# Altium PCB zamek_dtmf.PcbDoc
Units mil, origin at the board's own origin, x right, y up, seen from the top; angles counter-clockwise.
Board outline 6000 x 4000 mil, 2 copper layers (Top Layer, Bottom Layer); 26 components, 24 nets, 83 pads, 5 vias.
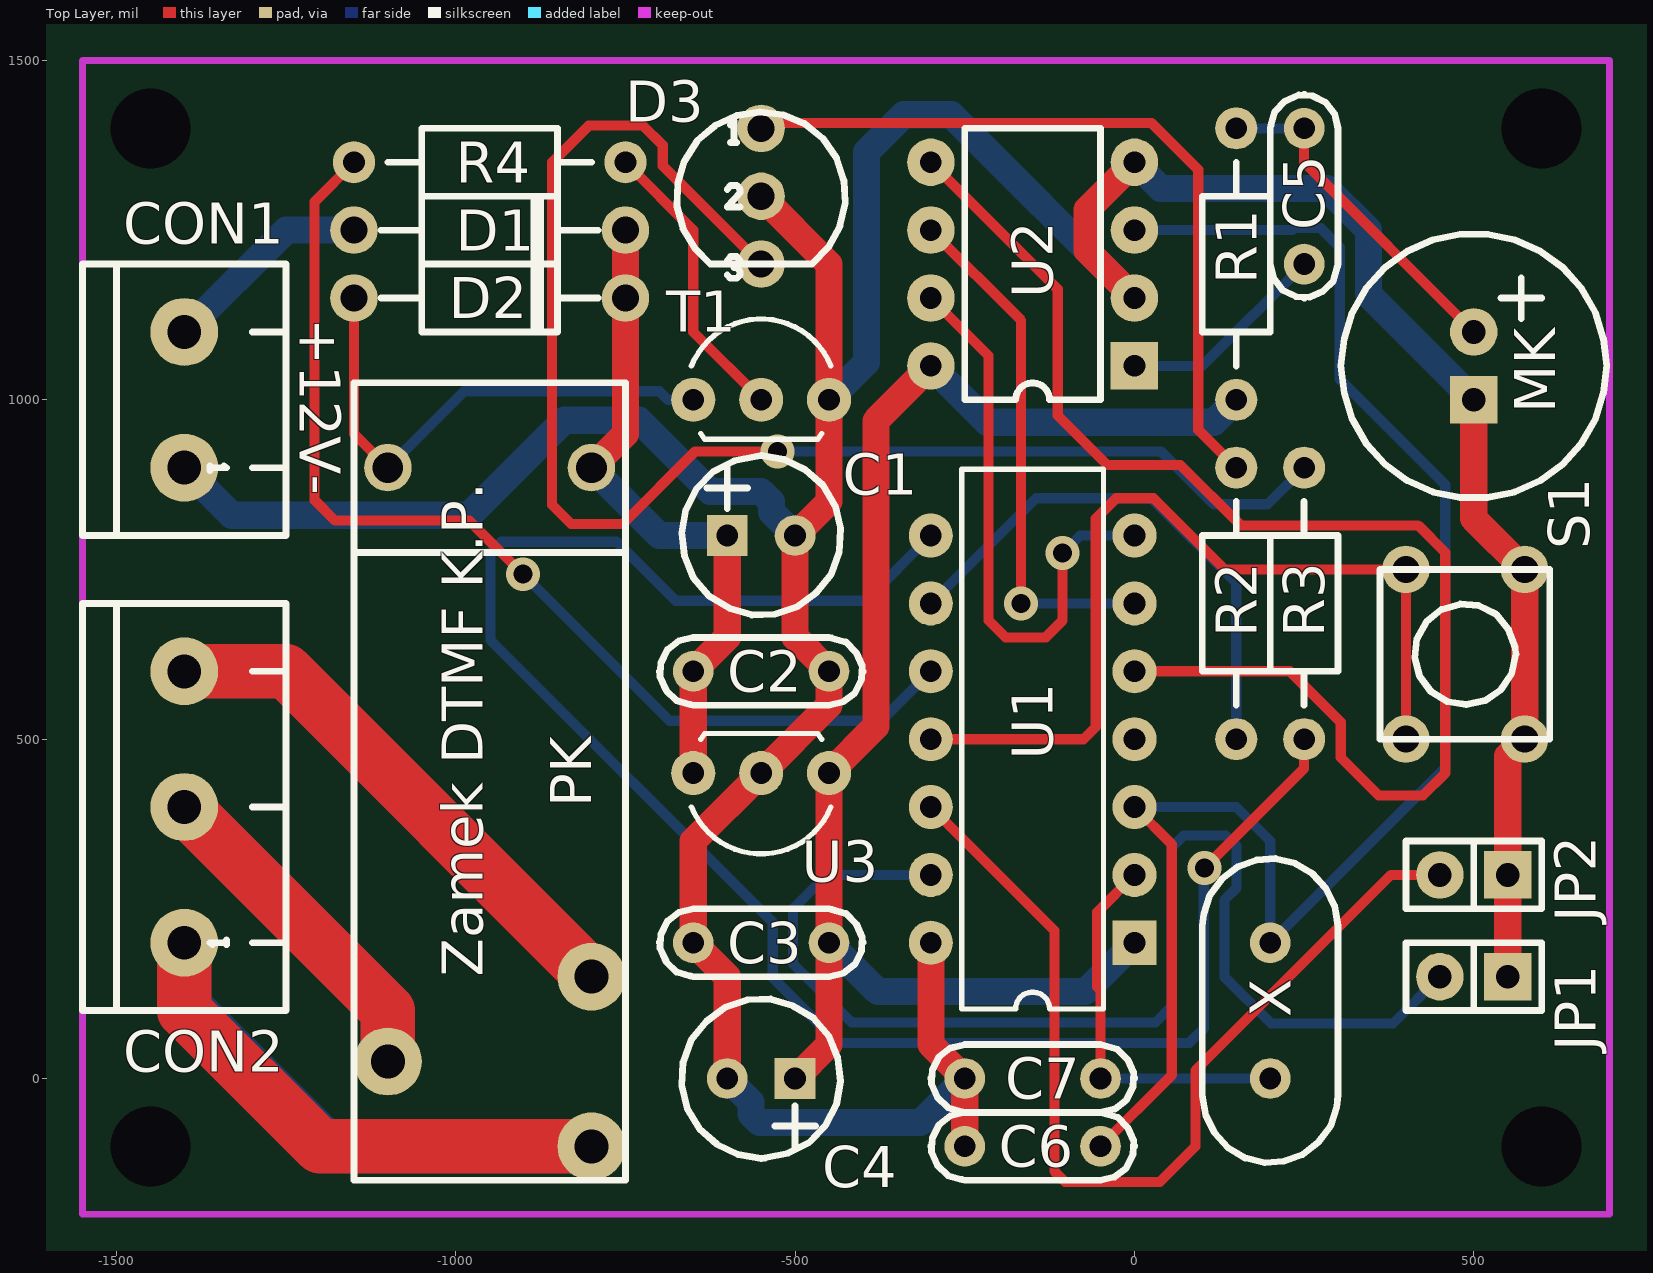
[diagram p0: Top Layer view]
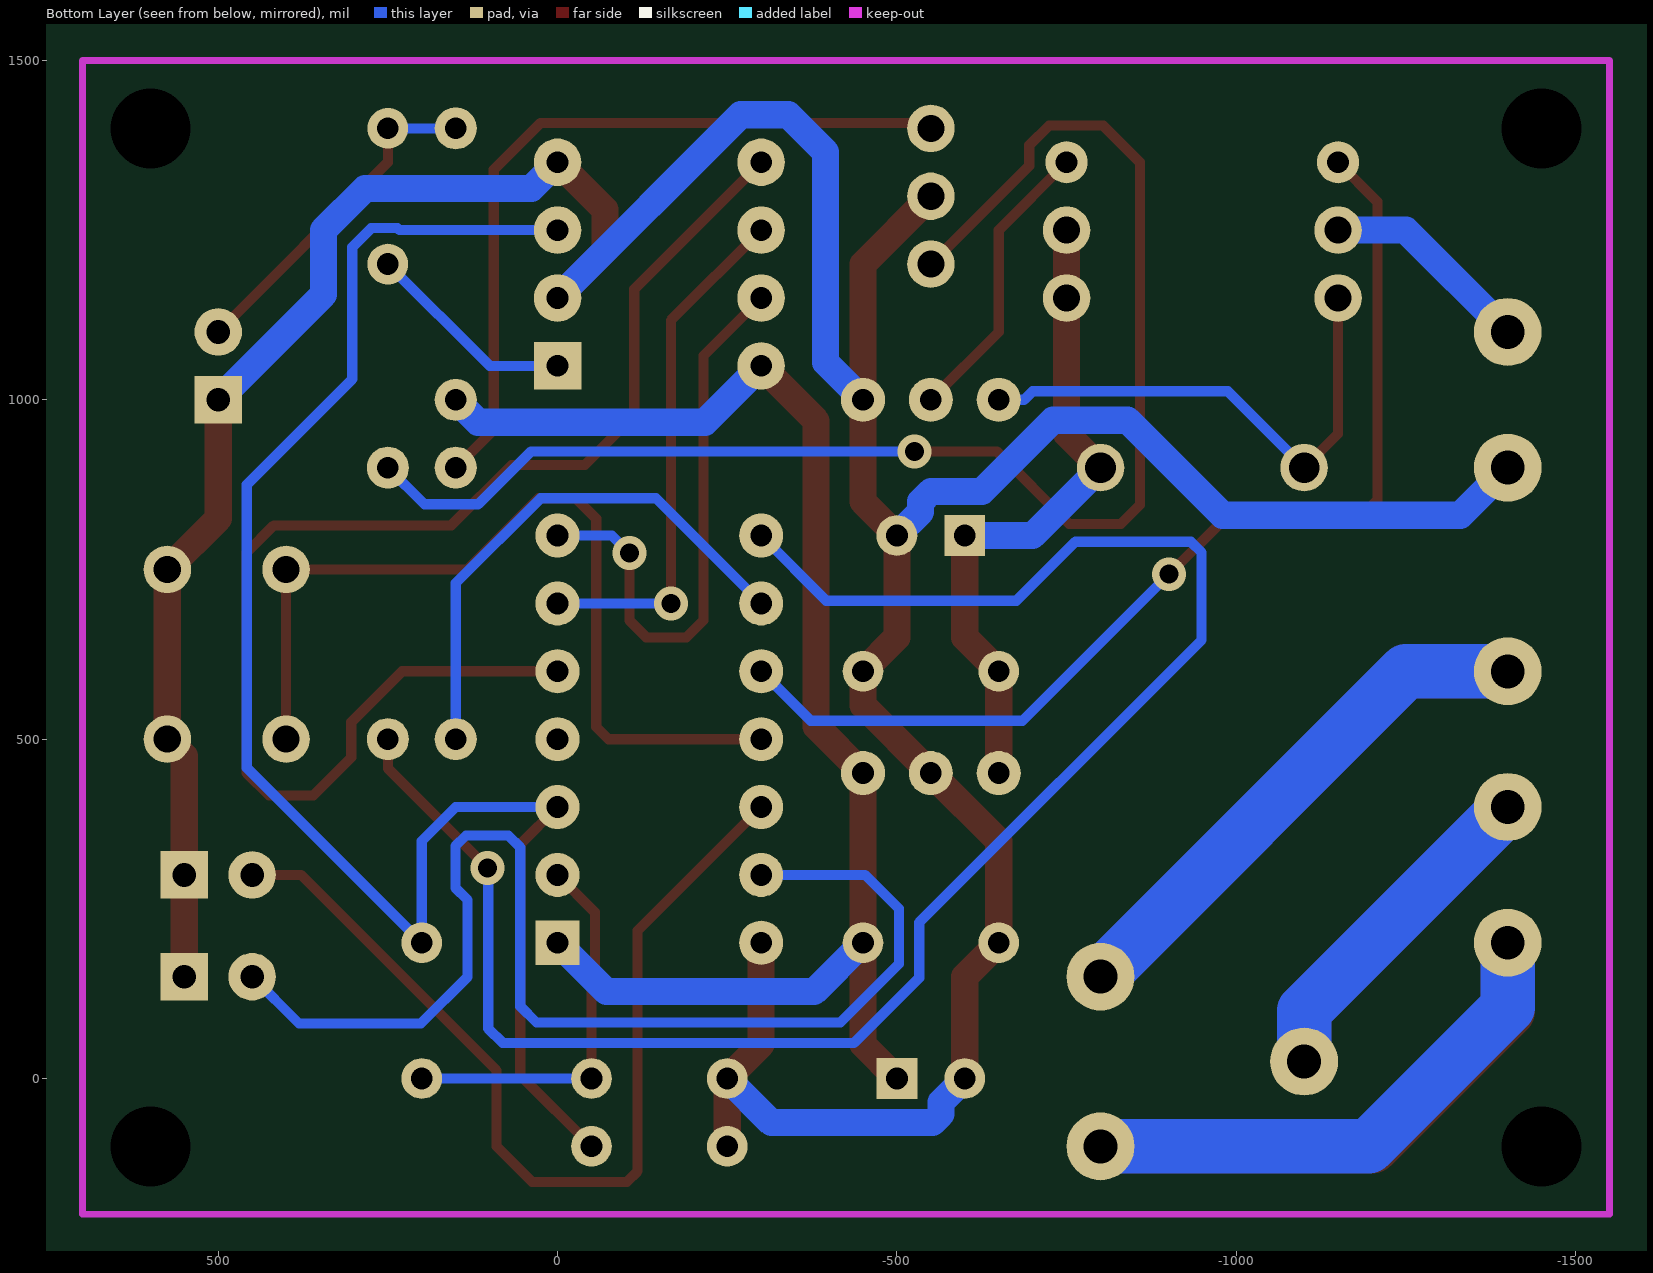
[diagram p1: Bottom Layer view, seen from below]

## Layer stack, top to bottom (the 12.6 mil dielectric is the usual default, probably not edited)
Top Layer: signal copper 1.4
Dielectric: dielectric 12.6, FR-4, Dk 4.8
Bottom Layer: signal copper 1.4

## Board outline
-2690,-1200 3310,-1200 3310,2800 -2690,2800

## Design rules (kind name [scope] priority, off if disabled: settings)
Clearance [All] p1: gap=20
ComponentClearance [All] p1: gap=10 collisioncheckmode=0
PolygonConnect [All] p1: connectstyle=Relief reliefconductorwidth=20 reliefentries=4 polygonreliefangle="90 Angle"
RoutingVias [All] p1: holewidth=28 width=50 viastyle="Through Hole" minholewidth=28 minwidth=50 maxholewidth=28 maxwidth=50
SolderMaskExpansion [All] p1: expansion=4
TestPointUsage [All] p1: valid=0 allowmultiple=FALSE
Testpoint [All] p1: side=15 testpointundercomponent=TRUE minsize=40 maxsize=100 preferedsize=60 minholesize=0 maxholesize=40 preferedholesize=32 testpointgrid=1 style=1023 order=-539222988
Width Width_2 [InNet('NetCON2_1') Or InNet('NetCON2_2') Or InNet('NetCON2_3')] p1: maxlimit=80 minlimit=10 preferedwidth=80
Width Width_1 [InNet('NetCON1_2') Or InNet('12V') Or InNet('GND') Or InNet('NetCON2_1') Or InNet('NetCON2_2') Or InNet('NetCON2_3') Or InNet('VCC')] p2: maxlimit=40 minlimit=10 preferedwidth=40
Width [All] p3: maxlimit=15 minlimit=10 preferedwidth=15
17 further rules are at their usual default settings.

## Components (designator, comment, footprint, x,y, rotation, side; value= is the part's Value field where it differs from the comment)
C1 "Cap Pol1" elektr1 -600,800 r90 top
C2 "Cap" cap1 -550,600 r180 top
C3 "Cap" cap1 -550,200 r0 top
C4 "Cap Pol1" elektr1 -500,0 r270 top
C5 "Cap" cap1 250,1300 r270 top
C6 "Cap" cap1 -150,-100 r0 top
C7 "Cap" cap1 -150,0 r0 top
CON1 "Header 2" con2-5 -1400,1000 r270 top
CON2 "Header 3" con3-5 -1400,400 r90 top
D1 "1N4007" dioda -950,1250 r0 top
D2 "1N4007" dioda -950,1150 r0 top
D3 "LED_2K" LED_2K -550,1400 r270 top
JP1 "JUMPER" SIP2 550,150 r180 top
JP2 "JUMPER" SIP2 550,300 r180 top
MK "Mic2" ELEKTR2 500,1050 r0 top
PK "RM96P-12" RM96P-12 -800,900 r90 top
R1 "Res2" r 150,1200 r270 top
R2 "Res2" R 150,700 r90 top
R3 "Res2" r 250,700 r90 top
R4 "Res2" r -950,1350 r0 top
S1 "SW-PB" key1 400,500 r0 top
T1 "BC547" TO-92C -650,1000 r90 top
U1 "PIC16F630-I/P" dip-14 -150,500 r90 top
U2 "MT3171BE" DIP8 0,1050 r180 top
U3 "78L05" TO-92C -450,450 r270 top
X "4,19MHz" xtal 200,100 r270 top

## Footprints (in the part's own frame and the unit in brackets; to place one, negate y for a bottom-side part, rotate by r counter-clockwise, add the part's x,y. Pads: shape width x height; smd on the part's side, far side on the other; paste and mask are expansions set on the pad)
cap1 [mil]
  round 60 hole 32: 1(-100,0) 2(100,0)
  silkscreen extent -150,-50 150,50
con2-5 [mil]
  round 100 hole 50: 1(100,0) 2(-100,0)
  silkscreen extent -200,-150 200,150
con3-5 [mil]
  round 100 hole 50: 1(-200,0) 2(0,0) 3(200,0)
  silkscreen extent -300,-150 300,150
dioda [mil]
  round 70 hole 40: 1(-200,0) 2(200,0)
  silkscreen extent -160,-50 160,50
DIP8 [mil]
  rect 70x70 hole 32: 1(0,0)
  round 70 hole 32: 2(0,-100) 3(0,-200) 4(0,-300) 5(300,-300) 6(300,-200) 7(300,-100) 8(300,0)
  silkscreen extent 50,-350 250,50
dip-14 [mil]
  rect 65x65 hole 32: 1(-300,-150)
  round 65 hole 32: 2(-200,-150) 3(-100,-150) 4(0,-150) 5(100,-150) 6(200,-150) 7(300,-150) 8(300,150) 9(200,150) 10(100,150) 11(0,150) 12(-100,150) 13(-200,150) 14(-300,150)
  silkscreen extent -398,-104 398,104
elektr1 [mil]
  rect 60x60 hole 32: 1(0,0)
  round 60 hole 32: 2(0,-100)
  silkscreen extent -117,-167 118,67
ELEKTR2 [mil]
  rect 70x70 hole 35: 1(0,-50)
  round 70 hole 35: 2(0,50)
  silkscreen extent -196,-194 196,194
key1 [mil]
  round 70 hole 40: 1(0,0) 1(0,250) 2(175,0) 2(175,250)
  silkscreen extent -38,0 212,250
LED_2K [mil]
  round 70 hole 40: 1(0,0) 2(100,0) 3(200,0)
  silkscreen extent -24,-124 221,124
r [mil]
  round 62 hole 32: 1(-200,0) 2(200,0)
  silkscreen extent -150,-50 150,50
R [mil]
  round 62 hole 32: 1(-200,0) 2(200,0)
  silkscreen extent -150,-50 150,50
RM96P-12 [mil]
  round 70 hole 45: 1(0,0) 2(0,300)
  round 100 hole 50: 3(-750,0) 4(-875,300) 5(-1000,0)
  silkscreen extent -1050,-50 125,350
SIP2 [mil]
  rect 70x70 hole 35: 1(0,0)
  round 70 hole 35: 2(100,0)
  silkscreen extent -50,-50 150,50
TO-92C [mil]
  round 65 hole 32: 1(0,0) 2(0,-100) 3(0,-200)
  silkscreen extent -58,-203 119,3
xtal [mil]
  round 60 hole 32: 1(-100,0) 2(100,0)
  silkscreen extent -224,-100 224,100

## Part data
C1 C4: library part ELECTRO2, "Electrolytic Capacitor"
C2 C3: library part CAP, "Capacitor"
C5 C6 C7: "Capacitor"
CON1: library part CON2, "Connector"
CON2: "Header, 3-Pin"
D1: library part DIODE, "Diode"
D2: library part LED1, "Typical RED GaAs LED"
D3: library part "Diode 1N4007", "1 Amp General Purpose Rectifier"
MK: "Microphone"
R1 R3 R4: "Resistor"
R2: library part "Res Adj2", "Variable Resistor"
S1: "Switch"
T1: library part NPN, "NPN Bipolar Transistor"
U1: library part PIC16F630-E/P, "FLASH-Based 8-Bit CMOS Microcontroller, 1K (x14-Bit words) FLASH, 64 Bytes SRAM, 14-Pin PDIP, 2.0 to 5.5V Supply Range, Extended Temperature"
U2: library part MT3170BE
U3: library part "Volt Reg", "Voltage Regulator"
X: library part XTAL, "Crystal Oscillator"

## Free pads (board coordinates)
  round 60 hole 118.11: 0(-1450,-100) 1(-1450,1400) 2(600,1400) 3(600,-100)

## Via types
v1: diameter 50, hole 28, Top Layer to Bottom Layer, 5 vias

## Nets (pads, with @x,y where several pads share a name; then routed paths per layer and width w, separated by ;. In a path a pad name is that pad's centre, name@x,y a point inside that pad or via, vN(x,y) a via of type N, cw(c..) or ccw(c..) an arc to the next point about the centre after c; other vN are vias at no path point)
12V: C1.1 C2.2 D1.2 D2.2 PK.1 U3.3 | length 982.8
  Top Layer w40: PK.1 -750,950 D2.2 D1.2 ; U3.3 C2.2 -600,650 C1.1
  Bottom Layer w40: PK.1 -700,800 C1.1
GND: C1.2 C2.1 C3.1 C4.2 C6.1 C7.1 CON1.1 D3.2 JP1.1 JP2.1 MK.1 S1.2 T1.3 U1.14 U2.2 U2.4 U3.2 | length 6054.8
  Top Layer w40: C4.2 -600,150 C3.1 -650,350 U3.2 -450,550 C2.1 -500,650 C1.2 -450,850 T1.3 -450,1200 D3.2 ; U1.14 -300,50 C7.1 C6.1 ; U2.2 -70,1220 -70,1280 U2.4 ; MK.1 500,825 575,750 575,500 550,475 JP2.1 JP1.1
  Bottom Layer w40: CON1.1 -1330,830 -980,830 -840,970 -730,970 -625,865 -550,865 -535,850 -535,835 C1.2 ; C4.2 -565,-35 -565,-52.5 -552.5,-65 -315,-65 C7.1 ; T1.3 -395,1055 -395,1365 -340,1420 -270,1420 U2.2 ; U2.4 38.58,1311.42 283.58,1311.42 345,1250 345,1155 MK.1
NetC5_1: C5.1 MK.2 R1.1 | length 503.6
  Top Layer w15: C5.1 250,1350 MK.2
  Bottom Layer w15: R1.1 C5.1
NetC5_2: C5.2 U2.1 | length 312.1
  Bottom Layer w15: U2.1 100,1050 C5.2
NetC6_2: C6.2 U1.3 U2.3 X.1 | length 2448.6
  Top Layer w15: C6.2 55,5 55,345 U1.3
  Bottom Layer w15: U1.3 150,400 200,350 X.1 458,458 458,875 302.5,1030.5 302.5,1225 274.5,1253 236,1253 233,1250 U2.3
NetC7_2: C7.2 U1.2 X.2 | length 574.9
  Top Layer w15: C7.2 -50,130 -55,135 -55,245 U1.2
  Bottom Layer w15: C7.2 X.2
NetCON1_2: CON1.2 D1.1 | length 312.1
  Bottom Layer w40: CON1.2 -1250,1250 D1.1
NetCON2_1: CON2.1 PK.5 | length 779.9
  Bottom Layer w80: CON2.1 -1400,105 -1195,-100 PK.5
NetCON2_2: CON2.2 PK.4 | length 499.3
  Top Layer w80: CON2.2 -1100,100 PK.4
NetCON2_3: CON2.3 PK.3 | length 786.4
  Bottom Layer w80: CON2.3 -1250,600 PK.3
NetD2_1: D2.1 PK.2 T1.1 | length 772.5
  Top Layer w15: D2.1 -1150,950 PK.2
  Bottom Layer w15: PK.2 -987.5,1012.5 -700,1012.5 -687.5,1000 T1.1
NetD3_1: D3.1 R2.2 | length 1142.8
  Top Layer w15: D3.1 -550,1408 25,1408 94,1339 94,956 R2.2
NetD3_3: D3.3 R3.2 | length 2156
  Top Layer w15: D3.3 -695,1345 -695,1375 -724,1404 -804,1404 -858,1350 -858,845 -830,817 -754,817 -647,924 v1(-526,924)
  Bottom Layer w15: v1(-526,924) 39,924 117,846 196,846 R3.2
NetJP1_2: JP1.2 U1.13 | length 1826.3
  Bottom Layer w15: U1.13 -453,300 -503,250 -503,169 -416.5,82.5 31,82.5 55,106.5 55,340.5 72.5,358 135,358 150.5,342.5 150.5,281 132.5,263 132.5,150 201.5,81 381,81 JP1.2
NetJP2_2: JP2.2 U1.12 | length 1439.6
  Top Layer w15: U1.12 -118,218 -118,-136.5 -102,-152.5 37.5,-152.5 90,-100 90,12 378,300 JP2.2
NetR2_1: R2.1 U1.9 | length 796
  Bottom Layer w15: U1.9 -145,855 25,855 150,730 R2.1
NetR3_1: R3.1 U1.8 | length 2701.5
  Top Layer w15: v1(103,310) 250,457 R3.1
  Bottom Layer w15: U1.8 -396,704 -676,704 -763,791 -933,791 -949,775 -949,646 -533,230 -533,148.57 -436.93,52.5 81,52.5 102,73.5 102,309 v1(103,310)
NetR4_1: R4.1 U1.10 | length 1594.9
  Top Layer w15: R4.1 -1208,1292 -1208,852 -1178,822 -980,822 v1(-901,743)
  Bottom Layer w15: v1(-901,743) -685,527 -373,527 U1.10
NetR4_2: R4.2 T1.2 | length 432.8
  Top Layer w15: R4.2 -650,1250 -650,1100 T1.2
NetS1_1: S1.1 U1.11 | length 1320.4
  Top Layer w15: U1.11 -75,500 -57,518 -57,825 -27,855 28,855 133,750 400,750 S1.1@400,500
NetU1_5: U1.5 U2.5 | length 2008.1
  Top Layer w15: U2.5 -113,1163 -113,977 -40,904 67.5,904 156.5,815 418,815 458,775 458,450 425,417 360,417 304,473 304,525 229,600 U1.5
NetU1_6: U1.6 U2.6 | length 772.1
  Top Layer w15: U2.6 -167,1117 v1(-167,700)
  Bottom Layer w15: v1(-167,700) U1.6
NetU1_7: U1.7 U2.7 | length 855.8
  Top Layer w15: U2.7 -215,1065 -215,675 -190,650 -130.81,650 -105.81,675 v1(-105.81,774.19)
  Bottom Layer w15: v1(-105.81,774.19) -80,800 U1.7
VCC: C3.2 C4.1 R1.2 U1.1 U2.8 U3.1 | length 2140.5
  Top Layer w40: C4.1 -450,50 C3.2 U3.1 -381,519 -381,969 U2.8
  Bottom Layer w40: C3.2 -378,128 -72,128 U1.1 ; U2.8 -217,967 117,967 R1.2
pads on no net: U1.4
copper on no net: | length 2068.5
  Top Layer w80: -1400,200 -1400,100 -1200,-100 -800,-100 ; -1400,600 -1250,600 -800,150
  Bottom Layer w80: -1400,400 -1100,100 -1100,25

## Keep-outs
Keep-Out Layer:
  lines w10: -1550,-200 -1550,1500 700,1500 700,-200 -1550,-200

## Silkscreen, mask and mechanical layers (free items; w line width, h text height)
Top Overlay:
  text "+12V-" at -1230,1120 h60 r270
  text "Zamek DTMF K.P." at -960,150 h60 r90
